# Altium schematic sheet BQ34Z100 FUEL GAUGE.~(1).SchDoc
size A3; SheetNumber: 13; SheetTotal: 14
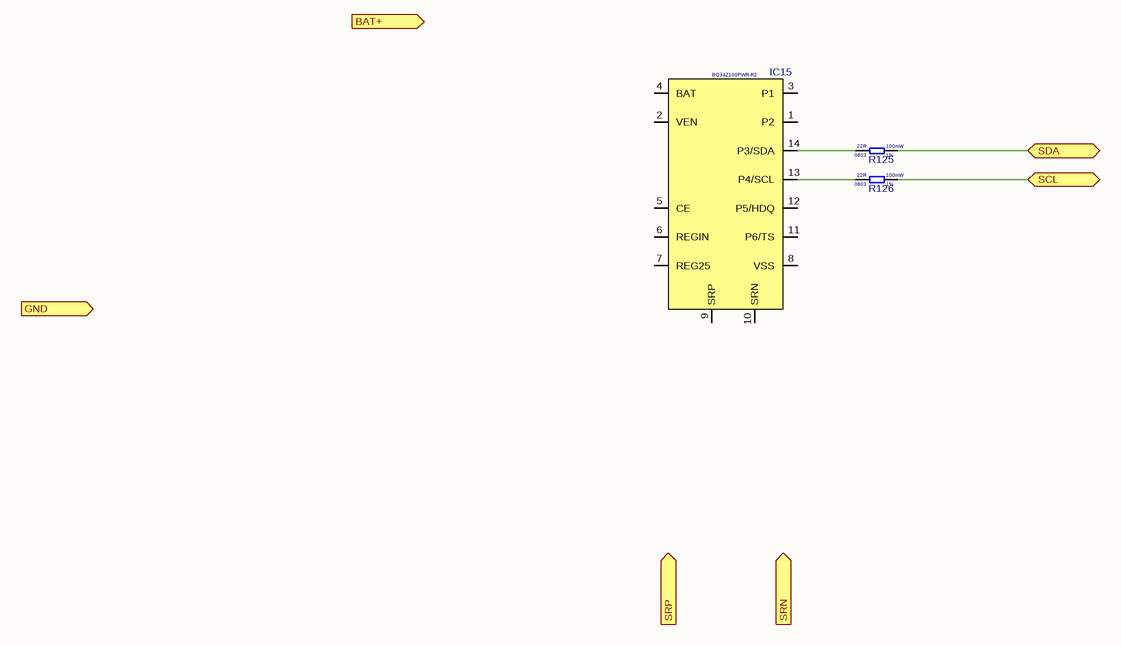
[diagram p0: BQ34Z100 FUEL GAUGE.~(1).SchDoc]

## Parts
IC15  BQ34Z100PWR-R2  [TSSOP-14]
R125  Resistance Tolerance: 1%  Resistance: 22R  Power Rating: 100mW  Case Code (Imperial): 0603  [RES_0603]  (hidden comment: 0603WAF220JT5E)
R126  Resistance Tolerance: 1%  Resistance: 22R  Power Rating: 100mW  Case Code (Imperial): 0603  [RES_0603]  (hidden comment: 0603WAF220JT5E)

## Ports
BAT+ (in, see BMS[4D], BAT+ to 5V1 STEP-DOWN[3B], BMS[1A], BQ76952 BMS[1A]), GND (in, see BMS[4D], 5V to 3V3 LDO[3B], BAT+ to 5V1 STEP-DOWN[3C], BQ76952 BMS[1D], MCU[1C]), SCL (bidir, see BMS[4C], BMS[8C], BQ76952 BMS[7C], MCU[1B]), SDA (bidir, see BMS[4C], BMS[8C], BQ76952 BMS[7C], MCU[1B]), SRN (in, see BMS[4D], BQ76952 BMS[5D]), SRP (in, see BMS[4D], BQ76952 BMS[5D])

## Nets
SCL: R126.2 ; port SCL
SDA: R125.2 ; port SDA
NetIC15_13: IC15.13(P4/SCL) R126.1
NetIC15_14: IC15.14(P3/SDA) R125.1

Not connected (* = marked no-connect by the designer): IC15 1(P2) 2(VEN) 3(P1) 4(BAT) 5(CE) 6(REGIN) 7(REG25) 8(VSS) 9(SRP) 10(SRN) 11(P6/TS) 12(P5/HDQ)

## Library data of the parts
IC15 = BQ34Z100PWR-R2: Fuel gauge; Manufacturer: Texas Instruments
R125 R126 = 0603WAF220JT5E: Res 22R 0603 1% 100mW 75V; Manufacturer: Uni-Royal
